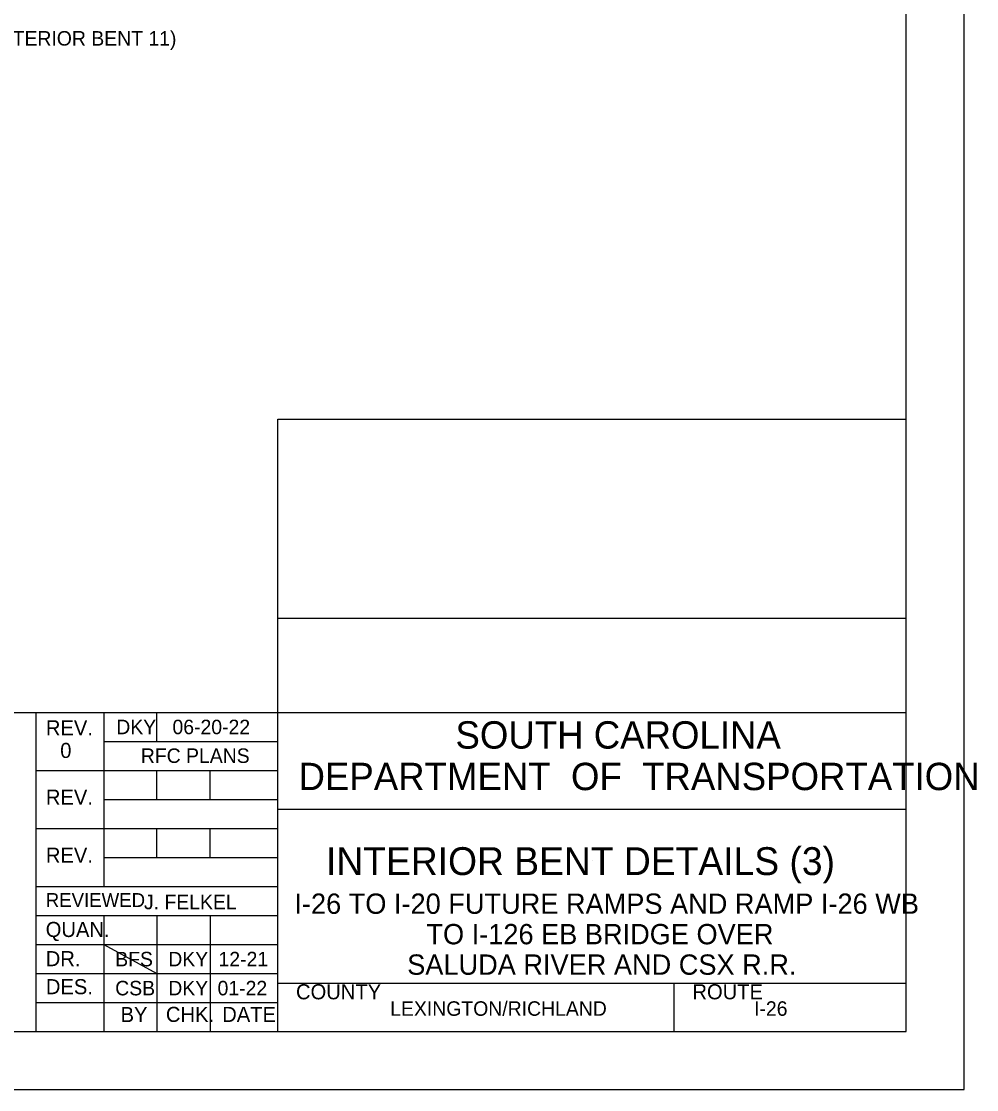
# Model space of a CAD drawing. Extents: x -133.1 to -97, y -1.7 to 20.3.
# Drawn here: x -105.27 to -97.03, y -1.69 to 7.51 of the extents above; entities that cross this region are included whole.
import ezdxf

# ---------------------------------------------------------------- set-up
doc = ezdxf.new("R2010")
doc.units = 0
for name, color, linetype in [('BR_AUTO DIMENSION', 7, 'Continuous'), ('BR_BORDER LINES', 7, 'Continuous'), ('BR_TEXT', 7, 'Continuous'), ('Level 31', 7, 'Continuous')]:
    doc.layers.add(name, color=color, linetype=linetype)

msp = doc.modelspace()

# ---------------------------------------------------------------- linework, layer by layer
at = {"layer": 'BR_BORDER LINES'}
for p, q in [((-97.6416, -1.191), (-97.6416, 19.8089)), ((-103.0585, -1.191), (-103.0585, 4.0855)), ((-103.0585, 4.0855), (-97.6416, 4.0855)), ((-103.0583, 2.3708), (-97.6416, 2.3708)), ((-110.5071, 1.5591), (-105.1419, 1.5591)), ((-105.1419, -1.191), (-105.1419, 1.5591)), ((-105.1419, 1.5591), (-97.6416, 1.5591)), ((-104.5585, 1.5591), (-104.5585, 0.059)), ((-104.1002, 1.3091), (-104.1002, 1.5591)), ((-104.5585, 1.3091), (-103.0585, 1.3091)), ((-105.1419, 1.0591), (-103.0585, 1.0591)), ((-104.1002, 0.809), (-104.1002, 1.0591)), ((-103.6418, 0.809), (-103.6418, 1.0591)), ((-104.5585, 0.809), (-103.0585, 0.809)), ((-103.0585, 0.7257), (-103.0585, 0.7257)), ((-103.0585, 0.7257), (-97.6414, 0.7257)), ((-105.1419, 0.559), (-103.0585, 0.559)), ((-104.1002, 0.309), (-104.1002, 0.559)), ((-103.6418, 0.309), (-103.6418, 0.559)), ((-104.5585, 0.309), (-103.0585, 0.309)), ((-105.1419, 0.059), (-103.0585, 0.059)), ((-105.1419, -0.191), (-103.0585, -0.191)), ((-104.5585, -0.191), (-104.5585, -1.191)), ((-104.1002, -0.191), (-104.1002, -1.191)), ((-103.6418, -0.191), (-103.6418, -1.191)), ((-105.1419, -0.441), (-103.0585, -0.441)), ((-105.1419, -0.691), (-103.0585, -0.691)), ((-103.0585, -0.7744), (-97.6416, -0.7744)), ((-102.9609, -0.7744), (-97.6416, -0.7744)), ((-99.6417, -1.191), (-99.6417, -0.7744)), ((-105.1419, -0.941), (-103.0585, -0.941)), ((-131.3076, -1.191), (-97.6416, -1.191))]:
    msp.add_line(p, q, dxfattribs=at)
at = {"layer": 'Level 31'}
for p, q in [((-100.3498, 0.2855), (-100.3498, 0.2855)), ((-104.5585, -0.441), (-104.1002, -0.691))]:
    msp.add_line(p, q, dxfattribs=at)
msp.add_lwpolyline([(-133.1409, -1.691), (-97.141, -1.691), (-97.141, 20.309), (-133.1409, 20.309)], close=True, dxfattribs=at)

# ---------------------------------------------------------------- texts
at = {"layer": 'BR_AUTO DIMENSION'}
msp.add_text('(INTERIOR BENT 11)', height=0.125, dxfattribs=at).set_placement((-105.5663, 7.3051))
at = {"layer": 'BR_TEXT'}
for s, height, p in [('REV.', 0.13001, (-105.0572, 1.362)), ('DKY', 0.12499, (-104.4502, 1.3715)), ('06-20-22', 0.12499, (-103.9658, 1.3715)), ('SOUTH CAROLINA', 0.23587, (-101.5266, 1.2475)), ('0', 0.13, (-104.9333, 1.167)), ('RFC PLANS', 0.12499, (-104.2386, 1.124)), ('DEPARTMENT  OF  TRANSPORTATION', 0.23587, (-102.8793, 0.8897)), ('REV.', 0.13001, (-105.0572, 0.7645)), ('REV.', 0.13001, (-105.0572, 0.2644)), ('INTERIOR BENT DETAILS (3)', 0.24, (-102.6425, 0.158)), ('REVIEWED', 0.12, (-105.0579, -0.1175)), ('I-26 TO I-20 FUTURE RAMPS AND RAMP I-26 WB', 0.175, (-102.915, -0.1761)), ('J. FELKEL', 0.125, (-104.2114, -0.1366)), ('QUAN.', 0.13001, (-105.0585, -0.3758)), ('TO I-126 EB BRIDGE OVER', 0.175, (-101.777, -0.4386)), ('DR.', 0.13001, (-105.0583, -0.6274)), ('BFS', 0.12499, (-104.4595, -0.6286)), ('DKY', 0.12499, (-104.002, -0.6286)), ('12-21', 0.12499, (-103.5689, -0.6286)), ('SALUDA RIVER AND CSX R.R.', 0.175, (-101.9427, -0.7011)), ('DES.', 0.13001, (-105.0572, -0.8687)), ('CSB', 0.12499, (-104.4595, -0.8786)), ('DKY', 0.12499, (-104.002, -0.8786)), ('01-22', 0.12499, (-103.5772, -0.8786)), ('COUNTY', 0.13001, (-102.9012, -0.9127)), ('ROUTE', 0.13001, (-99.4844, -0.9127)), ('BY', 0.13001, (-104.4132, -1.109)), ('CHK.', 0.13001, (-104.0224, -1.1077)), ('DATE', 0.13001, (-103.5372, -1.1076)), ('LEXINGTON/RICHLAND', 0.124995, (-102.089, -1.0548)), ('I-26', 0.12499, (-98.953, -1.0548))]:
    msp.add_text(s, height=height, dxfattribs=at).set_placement(p)

doc.saveas('drawing.dxf')
